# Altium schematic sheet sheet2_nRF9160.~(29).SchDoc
size A3; SheetNumber: 2; SheetTotal: 2
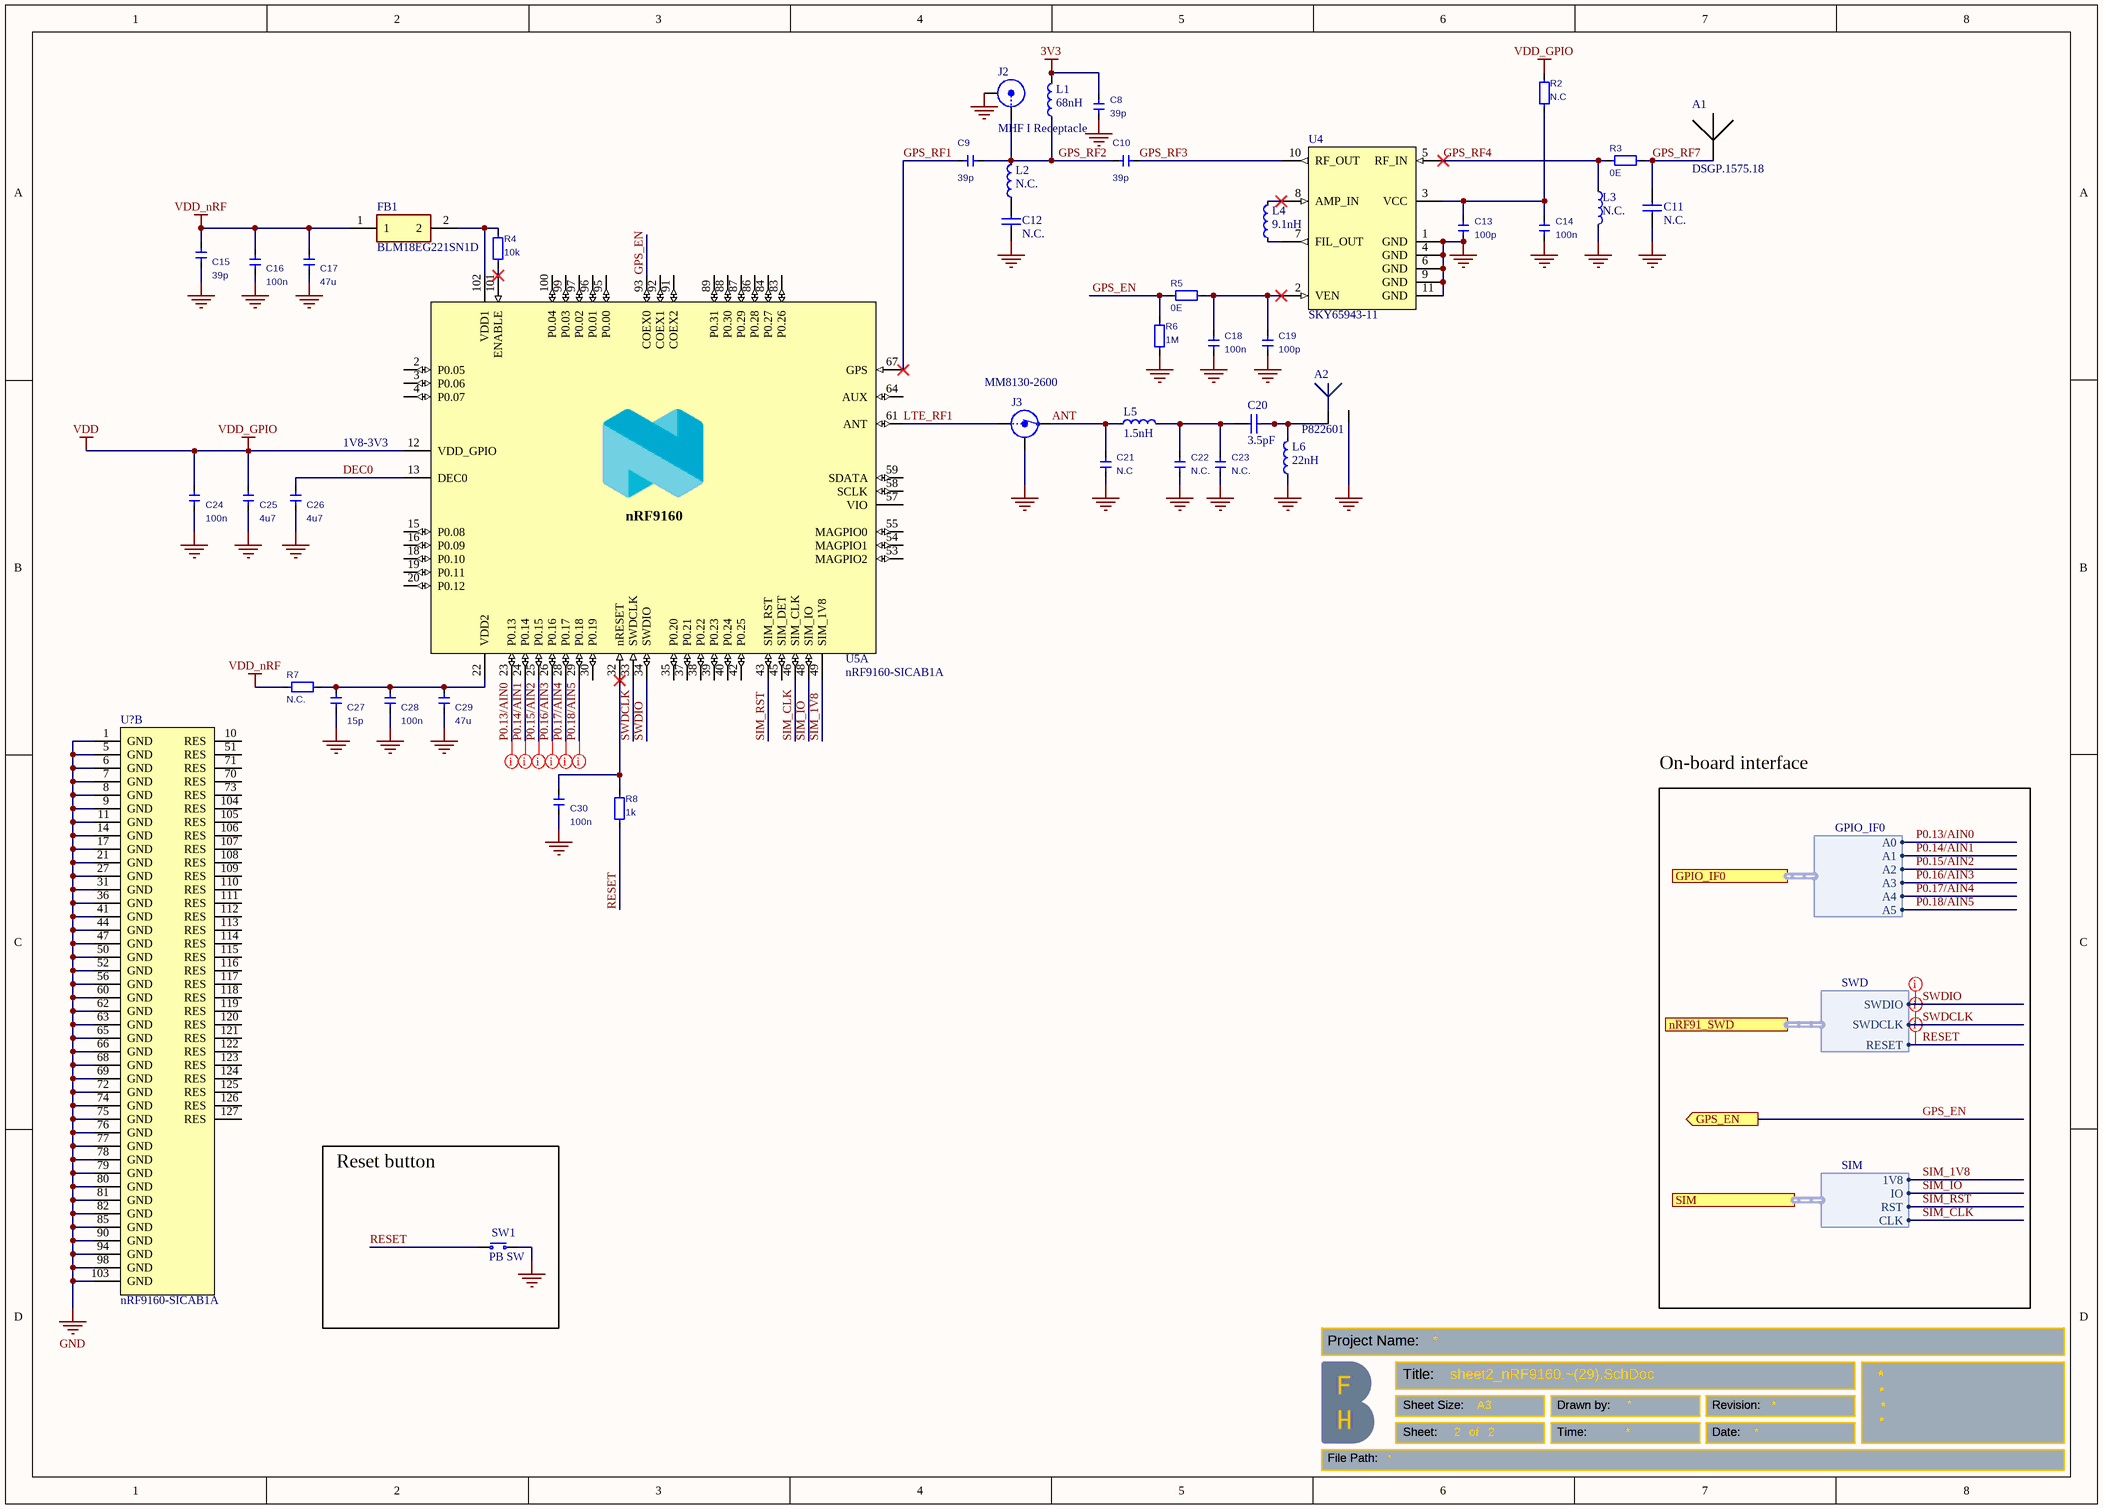
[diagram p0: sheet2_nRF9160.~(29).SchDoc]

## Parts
A1  DSGP.1575.18  [DSGP.1575.18]
A2  P822601  [P822601]
C8  39p  [0603(1608)C]
C9  39p  [0603(1608)C]
C10  39p  [0603(1608)C]
C11  N.C.  [CAPC1005X04L_NC]
C12  N.C.  [CAPC0603X03L_C_NC]
C13  100p  [0603(1608)C]
C14  100n  [0603(1608)C]
C15  39p  [0603(1608)C]
C16  100n  [0603(1608)C]
C17  47u  [1206(3216)C]
C18  100n  [0603(1608)C]
C19  100p  [0603(1608)C]
C20  3.5pF  [CAPC0603X03L_C]
C21  N.C  [0603(1608)C]
C22  N.C.  [0603(1608)C]
C23  N.C.  [0603(1608)C]
C24  100n  [0603(1608)C]
C25  4u7  [0603(1608)C]
C26  4u7  [0603(1608)C]
C27  15p  [0603(1608)C]
C28  100n  [0603(1608)C]
C29  47u  [1206(3216)C]
C30  100n  [0603(1608)C]
FB1  BLM18EG221SN1D  [BLM18SP221SN1B]
J2  MHF I Receptacle  [COAXIAL RF U.FL-R-SMT-1]
J3  MM8130-2600  [COAXIAL-SWF]
L1  68nH  [INDC1005X04L_WW]
L2  N.C.  [INDC1005X04L_NC]
L3  N.C.  [INDC1005X04L_NC]
L4  9.1nH  [INDC1005X04L_WW]
L5  1.5nH  [INDC0603X03L_C]
L6  22nH  [INDC0603X03L_C]
R2  N.C  [0603(1608)]
R3  0E  [0603(1608)]
R4  10k  [0603(1608)]
R5  0E  [0603(1608)]
R6  1M  [0603(1608)]
R7  N.C.  [0603(1608)]
R8  1k  [0603(1608)]
SW1  PB SW  [Switch-PB-6.2x6.3mm-SMD]
U4  SKY65943-11  [SKY65943-11]
U5  nRF9160-SICAB1A  [LGA50P1600X1050X104-161N]  (part A of 2)
U?  nRF9160-SICAB1A  [LGA50P1600X1050X104-161N]  (part B of 2)

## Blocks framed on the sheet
Reset button: SW1

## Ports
GPIO_IF0 (harness GPIO_IF0, see sheet4_sim_connections[1A]), GPS_EN (out, see sheet4_sim_connections[4C]), nRF91_SWD (harness SWD, see sheet4_sim_connections[4B]), SIM (harness SIM, see sheet4_sim_connections[3A])

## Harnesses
SIM: CLK, IO, 1V8, RST
SWD: SWDIO, SWDCLK, RESET
GPIO_IF0: A0, A1, A2, A3, A4, A5

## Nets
3V3: C8.2 L1.1
GND: A1.2(GND) A2.2 C8.1 C11.2 C12.1 C13.1 C14.1 C15.2 C16.2 C17.2 C18.1 C19.1 C21.1 C22.1 C23.1 C24.2 C25.2 C26.2 C27.2 C28.2 C29.2 C30.2 J2.2(Y) J3.2(Shield) L3.2 L6.1 R6.1 SW1.1(N.O) U4.1(GND) U4.4(GND) U4.6(GND) U4.9(GND) U4.11(GND) U?.1(GND) U?.5(GND) U?.6(GND) U?.7(GND) U?.8(GND) U?.9(GND) U?.11(GND) U?.14(GND) U?.17(GND) U?.21(GND) U?.27(GND) U?.31(GND) U?.36(GND) U?.41(GND) U?.44(GND) U?.47(GND) U?.50(GND) U?.52(GND) U?.56(GND) U?.60(GND) U?.62(GND) U?.63(GND) U?.65(GND) U?.66(GND) U?.68(GND) U?.69(GND) U?.72(GND) U?.74(GND) U?.75(GND) U?.76(GND) U?.77(GND) U?.78(GND) U?.79(GND) U?.80(GND) U?.81(GND) U?.82(GND) U?.85(GND) U?.90(GND) U?.94(GND) U?.98(GND) U?.103(GND)
VDD: C24.1 C25.1 R2.2 U5.12(VDD_GPIO)  [also labelled VDD_GPIO]
VDD_nRF: C15.1 C16.1 C17.1 FB1.1 R7.1
ANT: C21.2 J3.3(OUT) L5.1
DEC0: C26.1 U5.13(DEC0)
GPS_EN: R5.1 R6.2 U5.93(COEX0)
GPS_RF1: C9.2 U5.67(GPS)
GPS_RF2: C9.1 C10.2 J2.1(X) L1.2 L2.1
GPS_RF3: C10.1 U4.10(RF_OUT)
GPS_RF4: L3.1 R3.1 U4.5(RF_IN)
GPS_RF7: A1.1 C11.1 R3.2
LTE_RF1: J3.1(IN) U5.61(ANT)
P0.13/AIN0: U5.23(P0.13) ; port GPIO_IF0.A0
P0.14/AIN1: U5.24(P0.14) ; port GPIO_IF0.A1
P0.15/AIN2: U5.25(P0.15) ; port GPIO_IF0.A2
P0.16/AIN3: U5.26(P0.16) ; port GPIO_IF0.A3
P0.17/AIN4: U5.28(P0.17) ; port GPIO_IF0.A4
P0.18/AIN5: U5.29(P0.18) ; port GPIO_IF0.A5
RESET: R8.1 SW1.2(COM) ; port nRF91_SWD.RESET
SIM_1V8: U5.49(SIM_1V8) ; port SIM.1V8
SIM_CLK: U5.46(SIM_CLK) ; port SIM.CLK
SIM_IO: U5.48(SIM_IO) ; port SIM.IO
SIM_RST: U5.43(SIM_RST) ; port SIM.RST
SWDCLK: U5.33(SWDCLK) ; port nRF91_SWD.SWDCLK
SWDIO: U5.34(SWDIO) ; port nRF91_SWD.SWDIO
NetA2_1: A2.1 C20.2 L6.2
NetC12_2: C12.2 L2.2
NetC13_2: C13.2 C14.2 R2.1 U4.3(VCC)
NetC18_2: C18.2 C19.2 R5.2 U4.2(VEN)
NetC20_1: C20.1 C22.2 C23.2 L5.2
NetC27_1: C27.1 C28.1 C29.1 R7.2 U5.22(VDD2)
NetC30_1: C30.1 R8.2 U5.32(nRESET)
NetFB1_2: FB1.2 R4.1 U5.102(VDD1)
NetL4_1: L4.1 U4.8(AMP_IN)
NetL4_2: L4.2 U4.7(FIL_OUT)
NetR4_2: R4.2 U5.101(ENABLE)

Not connected (* = marked no-connect by the designer): U5 2(P0.05) 3(P0.06) 4(P0.07) 15(P0.08) 16(P0.09) 18(P0.10) 19(P0.11) 20(P0.12) 30(P0.19) 35(P0.20) 37(P0.21) 38(P0.22) 39(P0.23) 40(P0.24) 42(P0.25) 45(SIM_DET) 53(MAGPIO2) 54(MAGPIO1) 55(MAGPIO0) 57(VIO) 58(SCLK) 59(SDATA) 64(AUX) 83(P0.26) 84(P0.27) 86(P0.28) 87(P0.29) 88(P0.30) 89(P0.31) 91(COEX2) 92(COEX1) 95(P0.00) 96(P0.01) 97(P0.02) 99(P0.03) 100(P0.04); U? 10(RES) 51(RES) 70(RES) 71(RES) 73(RES) 104(RES) 105(RES) 106(RES) 107(RES) 108(RES) 109(RES) 110(RES) 111(RES) 112(RES) 113(RES) 114(RES) 115(RES) 116(RES) 117(RES) 118(RES) 119(RES) 120(RES) 121(RES) 122(RES) 123(RES) 124(RES) 125(RES) 126(RES) 127(RES)

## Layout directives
net class SWD: RESET, SWDCLK, SWDIO

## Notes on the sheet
- 1V8-3V3
- On-board interface
- GPS_EN

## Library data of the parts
A1 = DSGP.1575.18.4.A.02: 18 x 18 mm Low Profile GPS L1 / GALILEO E1 Passive Patch Antenna; Manufacturer: Taoglas; Part number IPS: 00000004435; Note: N.A.; Pad Count: 2
A2 = P822601: ANTENNA PRESTTA OCTABAND LTE; Manufacturer: Ethertronics; Part number IPS: 00000009001; Note: N.A.; Pad Count: 2
C8-C10 = C0603_1_39p_50V: Cer Chip Capacitor / 39p/ +-1%/ 50V; Manufacturer: Murata; Manufacturer P/N: GCM1885C1H390FA16J; Special Value 1: +-1%
C11 = C0402-N.C.: Not mounted; Manufacturer: N.A.; Assembly: Not mounted; Note: Chip Cap; Pad Count: 2
C12 = C0201-N.C.: Not mounted; Manufacturer: N.A.; Assembly: Not mounted; Note: Chip Cap; Pad Count: 2
C13 C19 = C0603_2_100p_50V: Cer Chip Capacitor / 100p/ +-1%/ 50V; Manufacturer: Murata; Manufacturer P/N: GCM1885C1H101FA16D; Special Value 1: +-1%
C14 C16 C18 C24 C28 C30 = C0603_5_100n_25V: Cer Chip Capacitor / 100n/ +-5%/ 25V; Manufacturer Part Number: CC0603KRX7R8BB104; Manufacturer 1: Yageo; Special Value 1: +-5%; Capacitance: 100nF; Tolerance: 10%; Dielectric: X7R
C15 = C0603_1_39p_50V: Cer Chip Capacitor / 15p/ +-1%/ 50V; Manufacturer: Murata; Manufacturer P/N: GCM1885C1H390FA16J; Special Value 1: +-1%
C17 C29 = C1206_7_47u_6.3V: Cer Chip Capacitor / 47u/ +-10%/ 6.3V; Manufacturer Part Number: CL31A476MQHNNNE; Manufacturer 1: Samsung; Special Value 1: +-20%; Material: Ceramic; Capacitance: 47uF; Tolerance: 20%; Dielectric: X5R
C20 = C0201-3.5p: Capacitor, NP0, ±0.1pF, 25V; Manufacturer: Murata; Manufacturer Part Number: GJM0335C1H3R5BB01E; Part number IPS: 00000001469; Artikkelnr Noca: N.A.; Pad Count: 2
C21-C23 = C0603: Cer Chip Capacitor
C25 C26 = C0603_6_4u7_25V: Cer Chip Capacitor / 4u7/ +-10%/ 25V; Manufacturer Part Number: CL10A475MA8NQNC; Manufacturer 1: Samsung; Special Value 1: +-10%; Capacitance: 4.7uF; Tolerance: 20%; Dielectric: X5R
C27 = C0603_1_39p_50V: Cer Chip Capacitor / 15p/ +-1%/ 50V; Manufacturer: Murata; Manufacturer P/N: GCM1885C1H390FA16J; Value: 39p; Special Value 1: +-1%
FB1 = BLM18EG221SN1D: Ferrite Bead; Manufacturer_Name: Murata Electronics
J2 = 20279-001E-03: Ultraminiature Coaxial Connector, 50 Ohm, SMD; Manufacturer: Wellshow; Part number IPS: 00000004436; Note: N.A.; Pad Count: 3
J3 = MM8130-2600: Coaxial Connector with Switch; Manufacturer: Murata; Part number IPS: 00000009955; Note: N.A.; Artikkelnr Noca: 55029011; Pad Count: 3
L1 = L0402-68n-Wirewound-Murata: Inductor, 140mA, ±2%, 1960mΩ, Q=20; Manufacturer: Murata; Manufacturer Part Number: LQW15AN68NG00; Part number IPS: 00000002494; Note: -55°C ~ 125°C; Artikkelnr Noca: N.A.; Pad Count: 2
L2 L3 = L0402-N.C.: Not mounted; Manufacturer: N.A.; Assembly: Not mounted; Pad Count: 2
L4 = L0402-9n1-Wirewound-Murata: Inductor, 540mA, ±2%, 140mΩ, Q=25; Manufacturer: Murata; Manufacturer Part Number: LQW15AN9N1G00; Part number IPS: 00000002497; Note: -55°C ~ 125°C; Artikkelnr Noca: N.A.; Pad Count: 2
L5 = L0201-1n5: Inductor, 650mA, ±0.1nH; Manufacturer: Murata; Manufacturer Part Number: LQP03TQ1N5B02D; Part number IPS: 00000000836; Note: N.A.; Pad Count: 2
L6 = L0201-22n: Chip Inductor; Manufacturer: N.A.; Part number IPS: 00000001478; Note: High frequency chip inductor ±10%; Pad Count: 2
R2 R3 R5 R7 = R0603_0_0E: Chip Resistor / 0E / 1% / 50V / 100mW / 0603(1608); Manufacturer Part Number: ERJ-3GEY0R00V; Manufacturer 1: Panasonic; Resistance: 0mR; Voltage Rating: 75V; Tolerance: 0%; Temperature Coefficient: 600ppm/°C
R4 = R0603_4_10k: Chip Resistor / 10k/ 1% / 50V / 100mW / 0603(1608); Manufacturer Part Number: RR0816P-103-D; Manufacturer 1: Susumu; Resistance: 10kR; Tolerance: 0.5%; Power Rating: 63mW; Voltage Rating: 75V; Temperature Coefficient: 25ppm/°C
R6 = R0603_6_1M: Chip Resistor / 1M/ 1% / 50V / 100mW / 0603(1608); Manufacturer Part Number: ERJ-8ENF1004V; Resistance: 1MR; Voltage Rating: 200V; Power Rating: 250mW; Temperature Coefficient: 100ppm/°C
R8 = R0603_3_1k: Chip Resistor / 1k/ 1% / 50V / 100mW / 0603(1608); Manufacturer: Panasonic; Manufacturer Part Number: ERA-8AEB102V; Resistance: 1kR; Power Rating: 250mW; Tolerance: 0.1%; Voltage Rating: 150V; Temperature Coefficient: 25ppm/°C
SW1 = Switch-PB-6.2x6.3mm-SMD: Tactile Switch, SPNO, SMD, 160gf, 6.2x6.3x2.5mm; Manufacturer: Dailywell; Manufacturer Part Number: TS604VM1-025BR-R; Part number IPS: 00000007812; Note: N.A.; Artikkelnr Noca: 50019106; Pad Count: 4
U4 = SKY65943-11: GNSS Low-Noise Amplifier Front-End Module with Integrated Pre-Filter and Post-Filter; Manufacturer: Skyworks; Part number IPS: 00000002997; Note: N.A.; Pad Count: 10
U5 U? = nRF9160-SICAB1A: Low power System-in-Package with integrated LTE-M/NB-IoT modem and GPS; Manufacturer: Nordic Semiconductor; Part number IPS: 80000002329; Note: N.A.; Pad Count: 161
